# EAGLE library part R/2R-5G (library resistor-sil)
R/2R Ladder 5 Murata RGSD10L
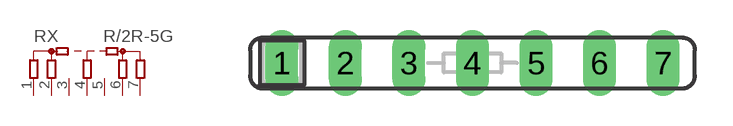
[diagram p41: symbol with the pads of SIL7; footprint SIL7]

Designator prefix RX

## R/2R-5G (OC_FARNELL: unknown; OC_NEWARK: unknown)  [SIL7]
1  IN  pas
2  B5  pas
3  B4  pas
4  B3  pas
5  B2  pas
6  B1  pas
7  OUT  pas

## Footprint SIL7 (pad centres in mm)
Single In Line
drill 0.813 long: 1 -7.62,0; 2 -5.08,0; 3 -2.54,0; 4 0,0; 5 2.54,0; 6 5.08,0; 7 7.62,0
